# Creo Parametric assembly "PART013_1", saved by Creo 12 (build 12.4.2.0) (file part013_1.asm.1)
Units: Custom; MM, KILOGRAM, SECS

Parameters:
  PTC_WM_ITERATION = "0"
  PTC_WM_VERSION = "-.0"
  PTC_WM_LIFECYCLE_STATE = "In Work"
  PTC_WM_LIFECYCLE = "MO_CADDocument"
  PTC_WM_CREATED_BY = "Maximilian Roepper (Z0017RMS: MO)"
  PTC_WM_CREATED_ON = "18-Sep-26 11:36:42 AM"
  PTC_WM_MODIFIED_BY = "Maximilian Roepper (Z0017RMS: MO)"
  PTC_WM_MODIFIED_ON = "18-Sep-26 11:36:46 AM"
  PDMLINKNUMBER = "PDM000071454907"
  PTC_WM_NUMBER = "PDM000071454907"

Other parameters: WEIGHT, WEIGHT_FACTOR, WEIGHT_ADD, MC_ERRORS, SUPPLIER

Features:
  1. coordinate system
  2. imported feature
  3. component "SHAPESTRING259_1"

Other named items: DRW_VIEW_ORG, ROUGH-GROB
